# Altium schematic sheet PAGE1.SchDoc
size 508 x 330 mm
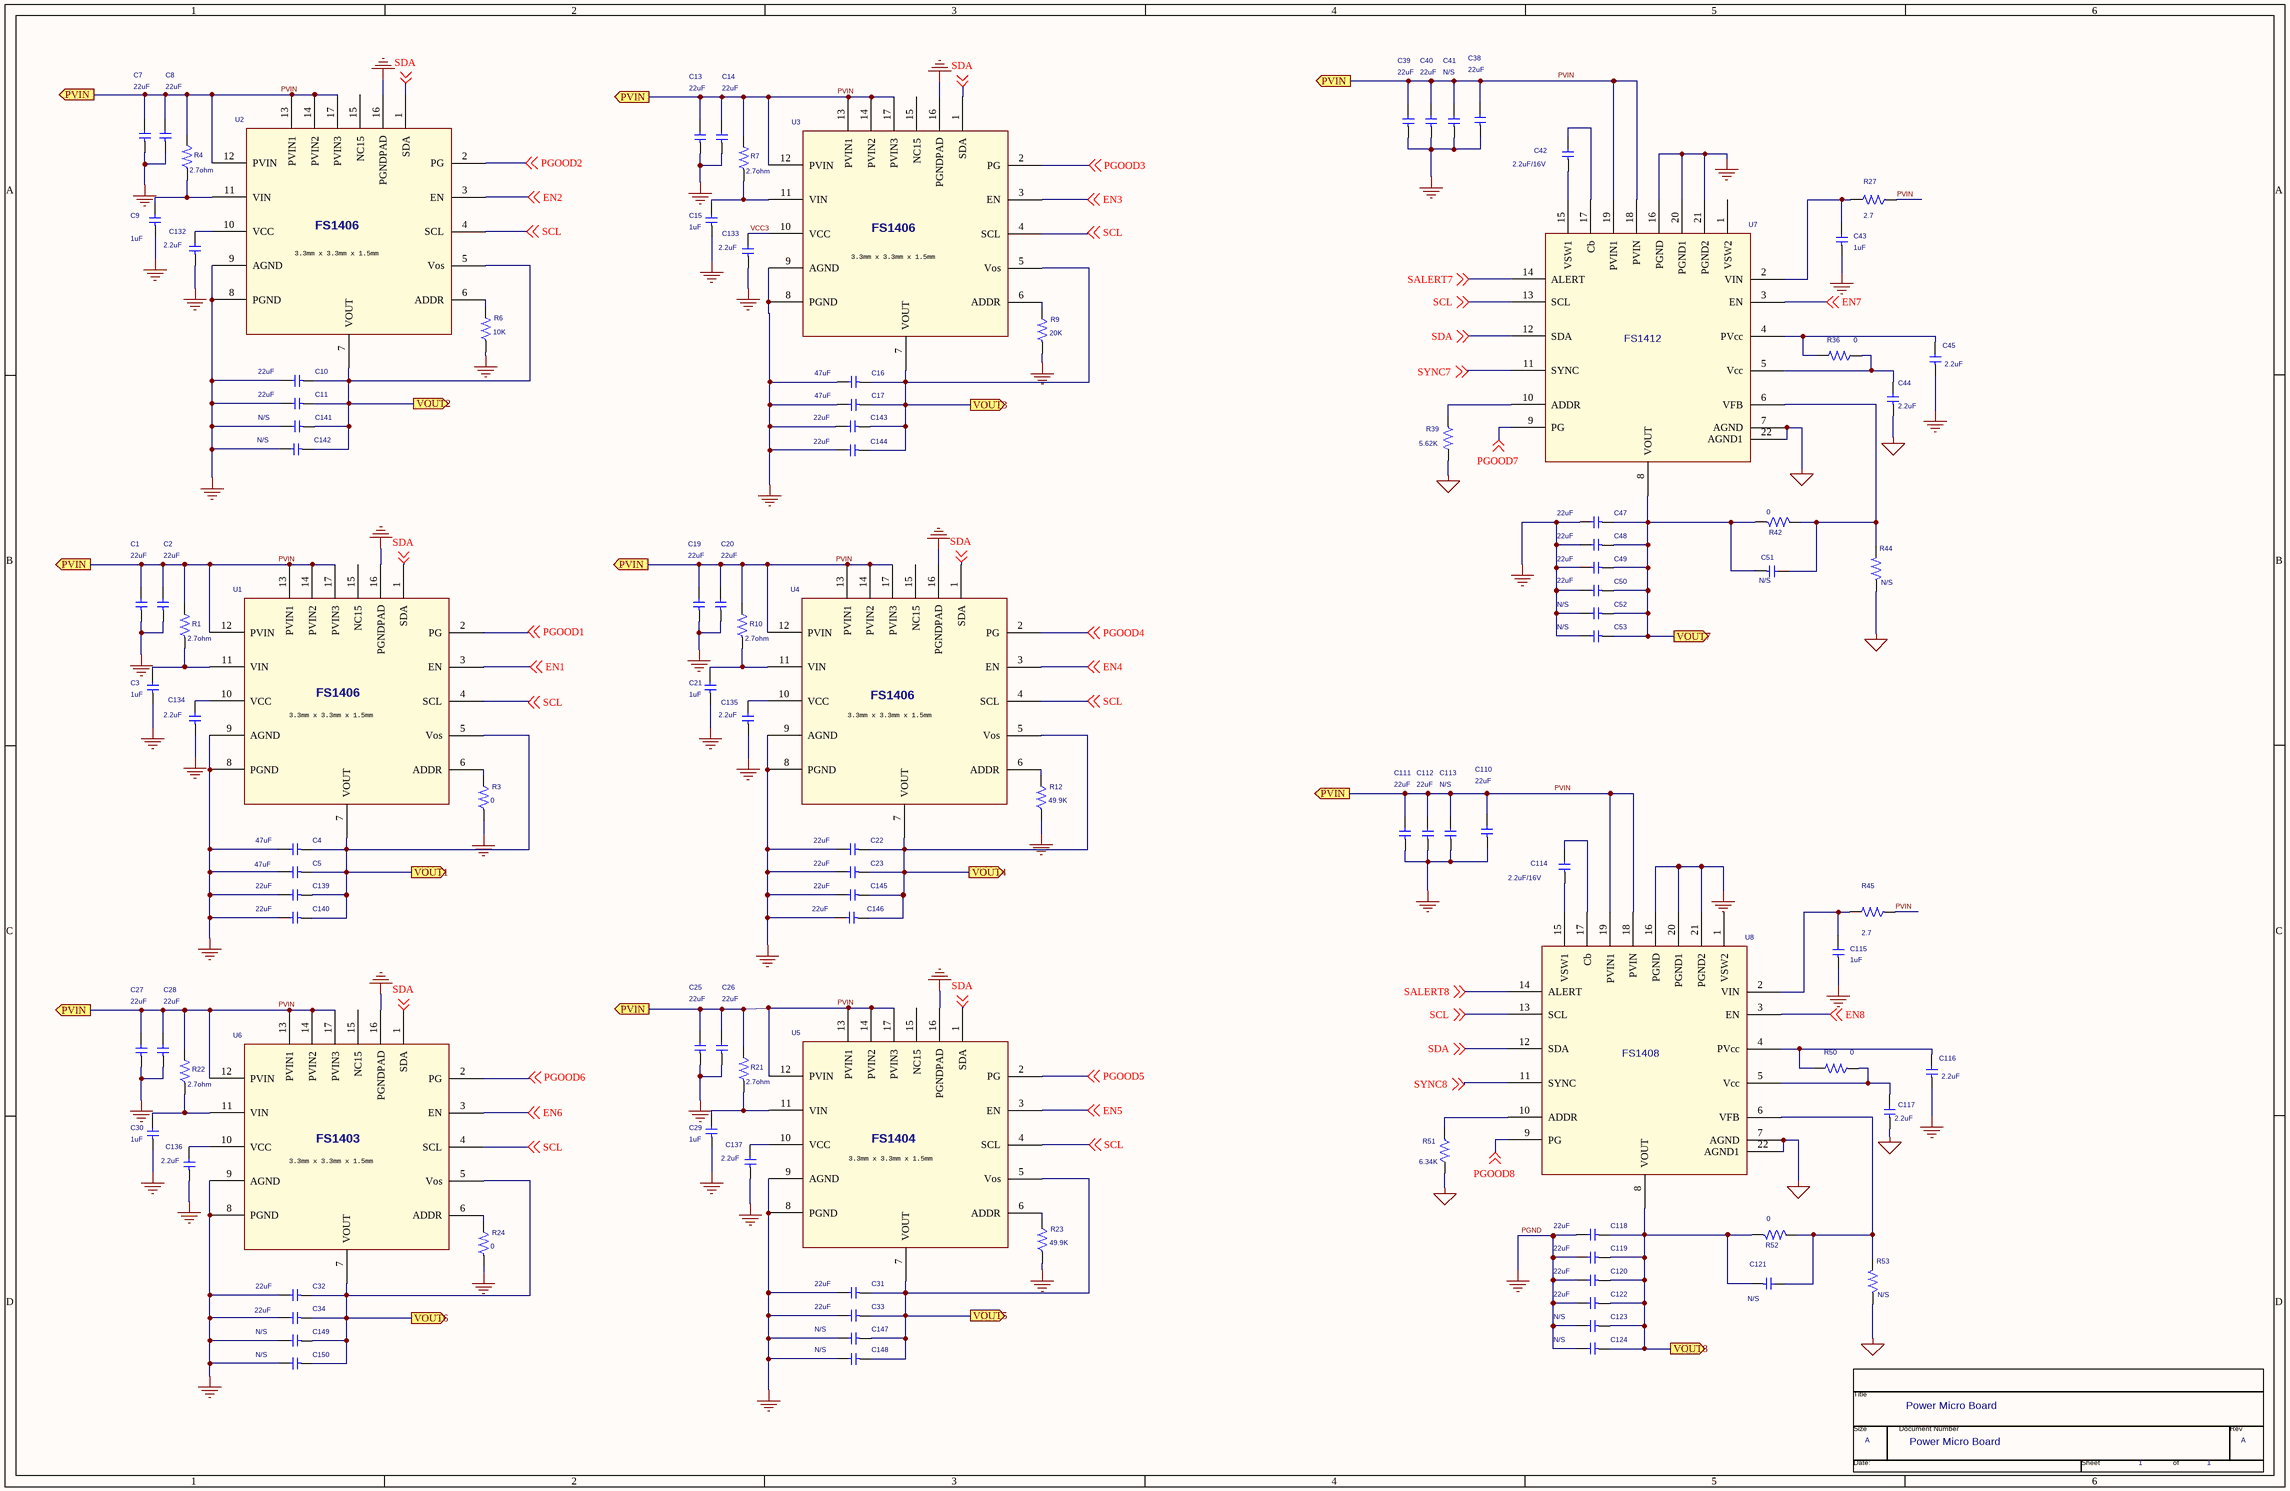
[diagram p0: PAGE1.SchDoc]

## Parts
*  Page Count: 1  Page Size: A  Title: Power Micro Board  (hidden comment: TitleBlock0)  (graphical)
C1  22uF  [0805]
C2  22uF  [0805]
C3  1uF  [0603]
C4  47uF  [0805]
C5  47uF  [0805]
C7  22uF  [0805]
C8  22uF  [0805]
C9  1uF  [0603]
C10  22uF  [0805]
C11  22uF  [0805]
C13  22uF  [0805]
C14  22uF  [0805]
C15  1uF  [0603]
C16  47uF  [0805]
C17  47uF  [0805]
C19  22uF  [0805]
C20  22uF  [0805]
C21  1uF  [0603]
C22  22uF  [0805]
C23  22uF  [0805]
C25  22uF  [0805]
C26  22uF  [0805]
C27  22uF  [0805]
C28  22uF  [0805]
C29  1uF  [0603]
C30  1uF  [0603]
C31  22uF  [0805]
C32  22uF  [0805]
C33  22uF  [0805]
C34  22uF  [0805]
C38  22uF  [0805]
C39  22uF  [0805]
C40  22uF  [0805]
C41  N/S  [0805]
C42  2.2uF/16V  [0603]
C43  1uF  [0603]
C44  2.2uF  [0402]
C45  2.2uF  [0402]
C47  22uF  [0805]
C48  22uF  [0805]
C49  22uF  [0805]
C50  22uF  [0805]
C51  N/S  [0402]
C52  N/S  [0805]
C53  N/S  [0805]
C110  22uF  [0805]
C111  22uF  [0805]
C112  22uF  [0805]
C113  N/S  [0805]
C114  2.2uF/16V  [0603]
C115  1uF  [0603]
C116  2.2uF  [0402]
C117  2.2uF  [0402]
C118  22uF  [0805]
C119  22uF  [0805]
C120  22uF  [0805]
C121  N/S  [0402]
C122  22uF  [0805]
C123  N/S  [0805]
C124  N/S  [0805]
C132  2.2uF  [0402]
C133  2.2uF  [0402]
C134  2.2uF  [0402]
C135  2.2uF  [0402]
C136  2.2uF  [0402]
C137  2.2uF  [0402]
C139  22uF  [0805]
C140  22uF  [0805]
C141  N/S  [0805]
C142  N/S  [0805]
C143  22uF  [0805]
C144  22uF  [0805]
C145  22uF  [0805]
C146  22uF  [0805]
C147  N/S  [0805]
C148  N/S  [0805]
C149  N/S  [0805]
C150  N/S  [0805]
R1  2.7ohm  [0402]
R3  0  [0402]
R4  2.7ohm  [0402]
R6  10K  [0402]
R7  2.7ohm  [0402]
R9  20K  [0402]
R10  2.7ohm  [0402]
R12  49.9K  [0402]
R21  2.7ohm  [0402]
R22  2.7ohm  [0402]
R23  49.9K  [0402]
R24  0  [0402]
R27  2.7  [0402]
R36  0  [0402]
R39  5.62K  [0402]
R42  0  [0402]
R44  N/S  [0402]
R45  2.7  [0402]
R50  0  [0402]
R51  6.34K  [0402]
R52  0  [0402]
R53  N/S  [0402]
U1  FS1406  [FS1406-02_NEW]
U2  FS1406  [FS1406-02_NEW]
U3  FS1406  [FS1406-02_NEW]
U4  FS1406  [FS1406-02_NEW]
U5  FS1404  [FS1406-02_NEW]
U6  FS1403  [FS1406-02_NEW]
U7  FS1412  [FS1412-POD]
U8  FS1408  [FS1412-POD]

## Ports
PVIN (out), VOUT1 (out), VOUT2 (out), VOUT3 (out), VOUT4 (out), VOUT5 (out), VOUT6 (out), VOUT7 (out), VOUT8 (out)

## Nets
AGND1: C44.1 R39.2 R44.1 U7.7(AGND) U7.22(AGND1)
AGND2: C117.1 R51.2 R53.1 U8.7(AGND) U8.22(AGND1)
PGND: C1.1 C2.1 C3.1 C4.2 C5.2 C7.1 C8.1 C9.1 C10.2 C11.2 C13.1 C14.1 C15.1 C16.2 C17.2 C19.1 C20.1 C21.1 C22.2 C23.2 C25.1 C26.1 C27.1 C28.1 C29.1 C30.1 C31.2 C32.2 C33.2 C34.2 C38.1 C39.1 C40.1 C41.1 C43.1 C45.1 C47.2 C48.2 C49.2 C50.2 C52.2 C53.2 C110.1 C111.1 C112.1 C113.1 C115.1 C116.1 C118.2 C119.2 C120.2 C122.2 C123.2 C124.2 C132.1 C133.1 C134.1 C135.1 C136.1 C137.1 C139.2 C140.2 C141.2 C142.2 C143.2 C144.2 C145.2 C146.2 C147.2 C148.2 C149.2 C150.2 R3.1 R6.1 R9.1 R12.1 R23.1 R24.1 U1.8(PGND) U1.9(AGND) U1.16(PGNDPAD) U2.8(PGND) U2.9(AGND) U2.16(PGNDPAD) U3.8(PGND) U3.9(AGND) U3.16(PGNDPAD) U4.8(PGND) U4.9(AGND) U4.16(PGNDPAD) U5.8(PGND) U5.9(AGND) U5.16(PGNDPAD) U6.8(PGND) U6.9(AGND) U6.16(PGNDPAD) U7.16(PGND) U7.20(PGND1) U7.21(PGND2) U8.16(PGND) U8.20(PGND1) U8.21(PGND2)
EN1: U1.3(EN) ; off-sheet EN1
EN2: U2.3(EN) ; off-sheet EN2
EN3: U3.3(EN) ; off-sheet EN3
EN4: U4.3(EN) ; off-sheet EN4
EN5: U5.3(EN) ; off-sheet EN5
EN6: U6.3(EN) ; off-sheet EN6
EN7: U7.3(EN) ; off-sheet EN7
EN8: U8.3(EN) ; off-sheet EN8
PGOOD1: U1.2(PG) ; off-sheet PGOOD1
PGOOD2: U2.2(PG) ; off-sheet PGOOD2
PGOOD3: U3.2(PG) ; off-sheet PGOOD3
PGOOD4: U4.2(PG) ; off-sheet PGOOD4
PGOOD5: U5.2(PG) ; off-sheet PGOOD5
PGOOD6: U6.2(PG) ; off-sheet PGOOD6
PGOOD7: U7.9(PG) ; off-sheet PGOOD7
PGOOD8: U8.9(PG) ; off-sheet PGOOD8
PVIN: C1.2 C2.2 C7.2 C8.2 C13.2 C14.2 C19.2 C20.2 C25.2 C26.2 C27.2 C28.2 C38.2 C39.2 C40.2 C41.2 C110.2 C111.2 C112.2 C113.2 R1.2 R4.2 R7.2 R10.2 R21.2 R22.2 R27.1 R45.1 U1.12(PVIN) U1.13(PVIN1) U1.14(PVIN2) U1.17(PVIN3) U2.12(PVIN) U2.13(PVIN1) U2.14(PVIN2) U2.17(PVIN3) U3.12(PVIN) U3.13(PVIN1) U3.14(PVIN2) U3.17(PVIN3) U4.12(PVIN) U4.13(PVIN1) U4.14(PVIN2) U4.17(PVIN3) U5.12(PVIN) U5.13(PVIN1) U5.14(PVIN2) U5.17(PVIN3) U6.12(PVIN) U6.13(PVIN1) U6.14(PVIN2) U6.17(PVIN3) U7.18(PVIN) U7.19(PVIN1) U8.18(PVIN) U8.19(PVIN1) ; port PVIN
SALERT7: U7.14(ALERT) ; off-sheet SALERT7
SALERT8: U8.14(ALERT) ; off-sheet SALERT8
SCL: U1.4(SCL) U2.4(SCL) U3.4(SCL) U4.4(SCL) U5.4(SCL) U6.4(SCL) U7.13(SCL) U8.13(SCL) ; off-sheet SCL
SDA: U1.1(SDA) U2.1(SDA) U3.1(SDA) U4.1(SDA) U5.1(SDA) U6.1(SDA) U7.12(SDA) U8.12(SDA) ; off-sheet SDA
SYNC7: U7.11(SYNC) ; off-sheet SYNC7
SYNC8: U8.11(SYNC) ; off-sheet SYNC8
VCC3: C133.2 U3.10(VCC)
VOUT1: C4.1 C5.1 C139.1 C140.1 U1.5(Vos) U1.7(VOUT) ; port VOUT1
VOUT2: C10.1 C11.1 C141.1 C142.1 U2.5(Vos) U2.7(VOUT) ; port VOUT2
VOUT3: C16.1 C17.1 C143.1 C144.1 U3.5(Vos) U3.7(VOUT) ; port VOUT3
VOUT4: C22.1 C23.1 C145.1 C146.1 U4.5(Vos) U4.7(VOUT) ; port VOUT4
VOUT5: C31.1 C33.1 C147.1 C148.1 U5.5(Vos) U5.7(VOUT) ; port VOUT5
VOUT6: C32.1 C34.1 C149.1 C150.1 U6.5(Vos) U6.7(VOUT) ; port VOUT6
VOUT7: C47.1 C48.1 C49.1 C50.1 C51.1 C52.1 C53.1 R42.1 U7.8(VOUT) ; port VOUT7
VOUT8: C118.1 C119.1 C120.1 C121.1 C122.1 C123.1 C124.1 R52.1 U8.8(VOUT) ; port VOUT8
NetC3_2: C3.2 R1.1 U1.11(VIN)
NetC9_2: C9.2 R4.1 U2.11(VIN)
NetC15_2: C15.2 R7.1 U3.11(VIN)
NetC21_2: C21.2 R10.1 U4.11(VIN)
NetC29_2: C29.2 R21.1 U5.11(VIN)
NetC30_2: C30.2 R22.1 U6.11(VIN)
NetC42_1: C42.1 U7.15(VSW1)
NetC42_2: C42.2 U7.17(Cb)
NetC43_2: C43.2 R27.2 U7.2(VIN)
NetC44_2: C44.2 R36.1 U7.5(Vcc)
NetC45_2: C45.2 R36.2 U7.4(PVcc)
NetC51_2: C51.2 R42.2 R44.2 U7.6(VFB)
NetC114_1: C114.1 U8.15(VSW1)
NetC114_2: C114.2 U8.17(Cb)
NetC115_2: C115.2 R45.2 U8.2(VIN)
NetC116_2: C116.2 R50.2 U8.4(PVcc)
NetC117_2: C117.2 R50.1 U8.5(Vcc)
NetC121_2: C121.2 R52.2 R53.2 U8.6(VFB)
NetC132_2: C132.2 U2.10(VCC)
NetC134_2: C134.2 U1.10(VCC)
NetC135_2: C135.2 U4.10(VCC)
NetC136_2: C136.2 U6.10(VCC)
NetC137_2: C137.2 U5.10(VCC)
NetR3_2: R3.2 U1.6(ADDR)
NetR6_2: R6.2 U2.6(ADDR)
NetR9_2: R9.2 U3.6(ADDR)
NetR12_2: R12.2 U4.6(ADDR)
NetR23_2: R23.2 U5.6(ADDR)
NetR24_2: R24.2 U6.6(ADDR)
NetR39_1: R39.1 U7.10(ADDR)
NetR51_1: R51.1 U8.10(ADDR)

Not connected (* = marked no-connect by the designer): U1 15(NC15); U2 15(NC15); U3 15(NC15); U4 15(NC15); U5 15(NC15); U6 15(NC15); U7 1(VSW2); U8 1(VSW2)

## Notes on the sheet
- (near U2) 3.3mm x 3.3mm x 1.5mm
- (near U3) 3.3mm x 3.3mm x 1.5mm
- (near U1) 3.3mm x 3.3mm x 1.5mm
- (near U4) 3.3mm x 3.3mm x 1.5mm
- (near U6) 3.3mm x 3.3mm x 1.5mm
- (near U5) 3.3mm x 3.3mm x 1.5mm

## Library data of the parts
C1 C2 C7 C8 C20 C25-C28 = C: 22uF-0805-16V-X5R-10%; Part Number: C2012X5R1C226K125AC; Manufacturer: TDK; VC2: 0; MAX_TEMP: CTMAX; SLOPE: CSMAX; KNEE: CBMAX; CURRENT: CIMAX; VOLTAGE: CMAX; PSpiceTemplate: C^@REFDES %1 %2 ?TOLERANCE¦C^@REFDES¦ @VALUE ?IC/IC=@IC/ TC=@TC1,@TC2 ?TOLERANCE¦\n.model C^@REFDES CAP C=1 DEV=@TOLERANCE% TC1=@TC1 TC2=@TC2 VC1=@VC1 VC2=@VC2¦; DIST: FLAT
C3 C21 C29 C30 C43 C115 = C: 1uF-0603-25V-X5R-10%; Manufacturer: Samsung; Part Number: CL10A105KA8NNNC; VC2: 0; MAX_TEMP: CTMAX; SLOPE: CSMAX; KNEE: CBMAX; CURRENT: CIMAX; VOLTAGE: CMAX; PSpiceTemplate: C^@REFDES %1 %2 ?TOLERANCE¦C^@REFDES¦ @VALUE ?IC/IC=@IC/ TC=@TC1,@TC2 ?TOLERANCE¦\n.model C^@REFDES CAP C=1 DEV=@TOLERANCE% TC1=@TC1 TC2=@TC2 VC1=@VC1 VC2=@VC2¦; DIST: FLAT
C4 = C: 47uF-0805-6.3V-X5R-20%; Manufacturer: TDK; Part Number: C2012X5R0J476M125AC; VC2: 0; MAX_TEMP: CTMAX; SLOPE: CSMAX; KNEE: CBMAX; CURRENT: CIMAX; VOLTAGE: CMAX; PSpiceTemplate: C^@REFDES %1 %2 ?TOLERANCE¦C^@REFDES¦ @VALUE ?IC/IC=@IC/ TC=@TC1,@TC2 ?TOLERANCE¦\n.model C^@REFDES CAP C=1 DEV=@TOLERANCE% TC1=@TC1 TC2=@TC2 VC1=@VC1 VC2=@VC2¦; DIST: FLAT
C5 C16 C17 = C: 47uF-0805-6.3V-X5R-20%; Part Number: C2012X5R0J476M125AC; Manufacturer: TDK; VC2: 0; MAX_TEMP: CTMAX; SLOPE: CSMAX; KNEE: CBMAX; CURRENT: CIMAX; VOLTAGE: CMAX; PSpiceTemplate: C^@REFDES %1 %2 ?TOLERANCE¦C^@REFDES¦ @VALUE ?IC/IC=@IC/ TC=@TC1,@TC2 ?TOLERANCE¦\n.model C^@REFDES CAP C=1 DEV=@TOLERANCE% TC1=@TC1 TC2=@TC2 VC1=@VC1 VC2=@VC2¦; DIST: FLAT
C9 C15 = C: 1uF-0603-25V-X5R-10%; Part Number: CL10A105KA8NNNC; Manufacturer: Samsung; VC2: 0; MAX_TEMP: CTMAX; SLOPE: CSMAX; KNEE: CBMAX; CURRENT: CIMAX; VOLTAGE: CMAX; PSpiceTemplate: C^@REFDES %1 %2 ?TOLERANCE¦C^@REFDES¦ @VALUE ?IC/IC=@IC/ TC=@TC1,@TC2 ?TOLERANCE¦\n.model C^@REFDES CAP C=1 DEV=@TOLERANCE% TC1=@TC1 TC2=@TC2 VC1=@VC1 VC2=@VC2¦; DIST: FLAT
C10 C22 C23 C31 C33 C52 C122 C140-C144 C147 = C: 22uF-0805-6.3V-X5R-10%; Part Number: C2012X5R0J226K125AB; Manufacturer: TDK; VC2: 0; MAX_TEMP: CTMAX; SLOPE: CSMAX; KNEE: CBMAX; CURRENT: CIMAX; VOLTAGE: CMAX; PSpiceTemplate: C^@REFDES %1 %2 ?TOLERANCE¦C^@REFDES¦ @VALUE ?IC/IC=@IC/ TC=@TC1,@TC2 ?TOLERANCE¦\n.model C^@REFDES CAP C=1 DEV=@TOLERANCE% TC1=@TC1 TC2=@TC2 VC1=@VC1 VC2=@VC2¦; DIST: FLAT
C11 C32 C34 C47-C50 C53 C118-C120 C123 C124 C139 C145 C146 C148-C150 = C: 22uF-0805-6.3V-X5R-10%; Manufacturer: TDK; Part Number: C2012X5R0J226K125AB; VC2: 0; MAX_TEMP: CTMAX; SLOPE: CSMAX; KNEE: CBMAX; CURRENT: CIMAX; VOLTAGE: CMAX; PSpiceTemplate: C^@REFDES %1 %2 ?TOLERANCE¦C^@REFDES¦ @VALUE ?IC/IC=@IC/ TC=@TC1,@TC2 ?TOLERANCE¦\n.model C^@REFDES CAP C=1 DEV=@TOLERANCE% TC1=@TC1 TC2=@TC2 VC1=@VC1 VC2=@VC2¦; DIST: FLAT
C13 C14 C19 = C: 22uF-0805-16V-X5R-10%; Manufacturer: TDK; Part Number: C2012X5R1C226K125AC; VC2: 0; MAX_TEMP: CTMAX; SLOPE: CSMAX; KNEE: CBMAX; CURRENT: CIMAX; VOLTAGE: CMAX; PSpiceTemplate: C^@REFDES %1 %2 ?TOLERANCE¦C^@REFDES¦ @VALUE ?IC/IC=@IC/ TC=@TC1,@TC2 ?TOLERANCE¦\n.model C^@REFDES CAP C=1 DEV=@TOLERANCE% TC1=@TC1 TC2=@TC2 VC1=@VC1 VC2=@VC2¦; DIST: FLAT
C38 C41 C110 C113 = C: 22uF-0805-25V-X5R-10%; Part Number: C2012X5R1E226M125AC; Manufacturer: TDK; VC2: 0; MAX_TEMP: CTMAX; SLOPE: CSMAX; KNEE: CBMAX; CURRENT: CIMAX; VOLTAGE: CMAX; PSpiceTemplate: C^@REFDES %1 %2 ?TOLERANCE¦C^@REFDES¦ @VALUE ?IC/IC=@IC/ TC=@TC1,@TC2 ?TOLERANCE¦\n.model C^@REFDES CAP C=1 DEV=@TOLERANCE% TC1=@TC1 TC2=@TC2 VC1=@VC1 VC2=@VC2¦; DIST: FLAT
C39 C40 C111 C112 = C: 22uF-0805-25V-X5R-10%; Manufacturer: TDK; Part Number: C2012X5R1E226M125AC; VC2: 0; MAX_TEMP: CTMAX; SLOPE: CSMAX; KNEE: CBMAX; CURRENT: CIMAX; VOLTAGE: CMAX; PSpiceTemplate: C^@REFDES %1 %2 ?TOLERANCE¦C^@REFDES¦ @VALUE ?IC/IC=@IC/ TC=@TC1,@TC2 ?TOLERANCE¦\n.model C^@REFDES CAP C=1 DEV=@TOLERANCE% TC1=@TC1 TC2=@TC2 VC1=@VC1 VC2=@VC2¦; DIST: FLAT
C42 C44 C45 C51 C114 C116 C117 C121 = C: VC2: 0; MAX_TEMP: CTMAX; SLOPE: CSMAX; KNEE: CBMAX; CURRENT: CIMAX; VOLTAGE: CMAX; PSpiceTemplate: C^@REFDES %1 %2 ?TOLERANCE¦C^@REFDES¦ @VALUE ?IC/IC=@IC/ TC=@TC1,@TC2 ?TOLERANCE¦\n.model C^@REFDES CAP C=1 DEV=@TOLERANCE% TC1=@TC1 TC2=@TC2 VC1=@VC1 VC2=@VC2¦; DIST: FLAT
C132-C137 = C: 2.2uF-0402-10V-X7S-10%; VC2: 0; MAX_TEMP: CTMAX; SLOPE: CSMAX; KNEE: CBMAX; CURRENT: CIMAX; VOLTAGE: CMAX; PSpiceTemplate: C^@REFDES %1 %2 ?TOLERANCE¦C^@REFDES¦ @VALUE ?IC/IC=@IC/ TC=@TC1,@TC2 ?TOLERANCE¦\n.model C^@REFDES CAP C=1 DEV=@TOLERANCE% TC1=@TC1 TC2=@TC2 VC1=@VC1 VC2=@VC2¦; DIST: FLAT
R1 R4 R10 R21 R22 R27 R45 = R: Res,0402,1/10 W,5%; Manufacturer: Panasonic; Part Number: ERJ-2GEJ2R7X; DIST: FLAT; PSpiceTemplate: R^@REFDES %1 %2 ?TOLERANCE¦R^@REFDES¦ @VALUE TC=@TC1,@TC2 ?TOLERANCE¦\n.model R^@REFDES RES R=1 DEV=@TOLERANCE% TC1=@TC1 TC2=@TC2¦; VOLTAGE: RVMAX; SLOPE: RSMAX; MAX_TEMP: RTMAX; POWER: RMAX; TC1: 0
R3 R24 = R: Res,0402,1/16 W,1%; Manufacturer: Panasonic; Part Number: ERJ-2GE0R00X; DIST: FLAT; PSpiceTemplate: R^@REFDES %1 %2 ?TOLERANCE¦R^@REFDES¦ @VALUE TC=@TC1,@TC2 ?TOLERANCE¦\n.model R^@REFDES RES R=1 DEV=@TOLERANCE% TC1=@TC1 TC2=@TC2¦; VOLTAGE: RVMAX; SLOPE: RSMAX; MAX_TEMP: RTMAX; POWER: RMAX
R6 = R: Res,0402,1/10 W,1%; Part Number: ERJ-2RKF1002X; Manufacturer: Panasonic; DIST: FLAT; PSpiceTemplate: R^@REFDES %1 %2 ?TOLERANCE¦R^@REFDES¦ @VALUE TC=@TC1,@TC2 ?TOLERANCE¦\n.model R^@REFDES RES R=1 DEV=@TOLERANCE% TC1=@TC1 TC2=@TC2¦; VOLTAGE: RVMAX; SLOPE: RSMAX; MAX_TEMP: RTMAX; POWER: RMAX; TC1: 0
R7 = R: Res,0402,1/10 W,5%; Part Number: ERJ-2GEJ2R7X; Manufacturer: Panasonic; DIST: FLAT; PSpiceTemplate: R^@REFDES %1 %2 ?TOLERANCE¦R^@REFDES¦ @VALUE TC=@TC1,@TC2 ?TOLERANCE¦\n.model R^@REFDES RES R=1 DEV=@TOLERANCE% TC1=@TC1 TC2=@TC2¦; VOLTAGE: RVMAX; SLOPE: RSMAX; MAX_TEMP: RTMAX; POWER: RMAX; TC1: 0
R9 = R: Res,0402,1/10 W,1%; Part Number: ERJ-2RKF2002X; Manufacturer: Panasonic; DIST: FLAT; PSpiceTemplate: R^@REFDES %1 %2 ?TOLERANCE¦R^@REFDES¦ @VALUE TC=@TC1,@TC2 ?TOLERANCE¦\n.model R^@REFDES RES R=1 DEV=@TOLERANCE% TC1=@TC1 TC2=@TC2¦; VOLTAGE: RVMAX; SLOPE: RSMAX; MAX_TEMP: RTMAX; POWER: RMAX; TC1: 0
R12 = R: Res,0402,1/10 W,1%; Manufacturer: Panasonic; Part Number: ERJ-2RKF4992X; DIST: FLAT; PSpiceTemplate: R^@REFDES %1 %2 ?TOLERANCE¦R^@REFDES¦ @VALUE TC=@TC1,@TC2 ?TOLERANCE¦\n.model R^@REFDES RES R=1 DEV=@TOLERANCE% TC1=@TC1 TC2=@TC2¦; VOLTAGE: RVMAX; SLOPE: RSMAX; MAX_TEMP: RTMAX; POWER: RMAX; TC1: 0
R23 = R: Res,0402,1/10 W,1%; Part Number: ERJ-2RKF4992X; Manufacturer: Panasonic; DIST: FLAT; PSpiceTemplate: R^@REFDES %1 %2 ?TOLERANCE¦R^@REFDES¦ @VALUE TC=@TC1,@TC2 ?TOLERANCE¦\n.model R^@REFDES RES R=1 DEV=@TOLERANCE% TC1=@TC1 TC2=@TC2¦; VOLTAGE: RVMAX; SLOPE: RSMAX; MAX_TEMP: RTMAX; POWER: RMAX; TC1: 0
R36 R42 R50 R52 = R: DIST: FLAT; PSpiceTemplate: R^@REFDES %1 %2 ?TOLERANCE¦R^@REFDES¦ @VALUE TC=@TC1,@TC2 ?TOLERANCE¦\n.model R^@REFDES RES R=1 DEV=@TOLERANCE% TC1=@TC1 TC2=@TC2¦; VOLTAGE: RVMAX; SLOPE: RSMAX; MAX_TEMP: RTMAX; POWER: RMAX
R39 = R: Res,0402,1/16 W,1%; Part Number: ERJ-2GE0R00X; Manufacturer: Panasonic; DIST: FLAT; PSpiceTemplate: R^@REFDES %1 %2 ?TOLERANCE¦R^@REFDES¦ @VALUE TC=@TC1,@TC2 ?TOLERANCE¦\n.model R^@REFDES RES R=1 DEV=@TOLERANCE% TC1=@TC1 TC2=@TC2¦; VOLTAGE: RVMAX; SLOPE: RSMAX; MAX_TEMP: RTMAX; POWER: RMAX; TC1: 0
R44 R53 = R: DIST: FLAT; PSpiceTemplate: R^@REFDES %1 %2 ?TOLERANCE¦R^@REFDES¦ @VALUE TC=@TC1,@TC2 ?TOLERANCE¦\n.model R^@REFDES RES R=1 DEV=@TOLERANCE% TC1=@TC1 TC2=@TC2¦; VOLTAGE: RVMAX; SLOPE: RSMAX; MAX_TEMP: RTMAX; POWER: RMAX; TC1: 0
R51 = R: Res,0402,1/16 W,1%; Manufacturer: Panasonic; Part Number: ERJ-2GE0R00X; DIST: FLAT; PSpiceTemplate: R^@REFDES %1 %2 ?TOLERANCE¦R^@REFDES¦ @VALUE TC=@TC1,@TC2 ?TOLERANCE¦\n.model R^@REFDES RES R=1 DEV=@TOLERANCE% TC1=@TC1 TC2=@TC2¦; VOLTAGE: RVMAX; SLOPE: RSMAX; MAX_TEMP: RTMAX; POWER: RMAX; TC1: 0
U1 = FS1206_18
U2 = FS1206_16
U3 = FS1206_17
U4 = FS1206_19
U5 = FS1206_21
U6 = FS1206_20
U7 U8 = FS1206_11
